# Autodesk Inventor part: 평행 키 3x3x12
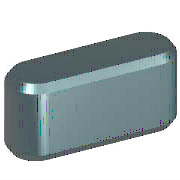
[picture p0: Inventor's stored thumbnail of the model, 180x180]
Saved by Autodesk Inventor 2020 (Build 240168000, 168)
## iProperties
Created: 2012-02
Part Number: 평행 키 3x3x12
Material: 강철, 연강
Description: 평행 키
Document SubType Name: Modeling
Standard: JIS B 1301
Designer: mdu-01
Standards Organization: JIS
Language: ko-KR
Size Designation: 3x3x12
Categories: <MemberInstance><Categories><Category DisplayName="샤프트 부품" InternalName="7f7aeb1f-a693-4053-b835-cee3144e0d98" Mnemonic="SHFT"><Category DisplayName="키" Interna
Density: 1 g/cm^3
Appearance: 기본값(1)
IsCustomPart: 1
Author: mdu-01
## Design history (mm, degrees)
workplane "Work Plane1"
workplane "Work Plane2"
sketch "스케치1"
  geometry: L1 (1.5, 1.5)-(10.5, 1.5); L2 (10.5, -1.5)-(1.5, -1.5); L3 (0, 9.4)-(0, -7.4) reference; L4 (-5, 0)-(30, 0) reference; L5 (12, 0)-(12, 7); A1 r 1.5 centre (1.5, 0) between (1.5, 1.5) and (1.5, -1.5); A2 r 1.5 centre (10.5, 0) between (10.5, -1.5) and (10.5, 1.5)
  constraints: 6 end point, 5 point on circle, 4 tangent, 3 point on line, 2 centre point, 1 horizontal, 1 parallel, 1 perpendicular
  dimensions: "d0" = 1.5 radius of A1 (= 0.5 x PB); "d13" = 1.5 radius of A2 (= 0.5 x PB); "d14" = 12 distance between parallel lines of L5 L3 (= NLG)
extrude "본체1" new body sketch "스케치1" taper "d3" = 0 deg; stored distance "d4" = 10
workplane "Work Plane3"
body "Solid1"
chamfer "모따기1" distance "d8" = 0.25 (= PHH); stored, may be unused: second distance "d9" = 0.25 (= PHH), angle "d15" = 45 deg
other parameters: "d1" = -1.8 (= -PNT), "d2" = 1.2 (= PH - PNT), "NLG" = 12 [user parameter; used in 3 equation terms], "PB" = 3 [user parameter; used in 2 equation terms], "PNT" = 1.8 [user parameter; used in 2 equation terms], "PH" = 3 [user parameter; used in 1 equation term], "PHH" = 0.25 [user parameter; used in 2 equation terms], "d10" = 0, "d16" = 0, "d17" = 0, "d18" = 0, "WDMIN" = 8 [user parameter], "PLB2" = 12 (= NLG) [user parameter], "PLB1" = 12 (= NLG) [user parameter], "RR" = 0.08 [user parameter], "PUEB" = 1.4 [user parameter]
